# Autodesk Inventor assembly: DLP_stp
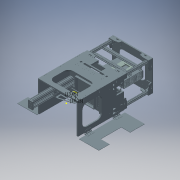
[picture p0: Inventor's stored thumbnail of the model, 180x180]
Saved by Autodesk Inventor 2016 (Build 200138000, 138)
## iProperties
Created: 2016-01
Part Number: DLP_stp
Document SubType Name: Assembly
Designer: John
Sending System: SIEMENS PLM Software NX 7.5
Preprocessor: ST-DEVELOPER v11
Title: DLP_stp.stp
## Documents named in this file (21)
- D:\3D Printer Designs\John Ledden Designs\DLP Printer\V2\DLP_stp.iam
- D:\3D Printer Designs\John Ledden Designs\DLP Printer\V2\VAT_ASSM.iam
- D:\3D Printer Designs\John Ledden Designs\DLP Printer\V2\91185A909_step.ipt
- D:\3D Printer Designs\John Ledden Designs\DLP Printer\V2\FRAME_ZMount.ipt
- D:\3D Printer Designs\John Ledden Designs\DLP Printer\V2\FRAME_SideWindow.ipt
- D:\3D Printer Designs\John Ledden Designs\DLP Printer\V2\VatHolder.ipt
- D:\3D Printer Designs\John Ledden Designs\DLP Printer\V2\FRAME_Rear.ipt
- D:\3D Printer Designs\John Ledden Designs\DLP Printer\V2\Frame_Mid.ipt
- D:\3D Printer Designs\John Ledden Designs\DLP Printer\V2\CornerBracket.ipt
- D:\3D Printer Designs\John Ledden Designs\DLP Printer\V2\CornerBracket_Projector.ipt
- D:\3D Printer Designs\John Ledden Designs\DLP Printer\V2\TSlot_300mm.ipt
- D:\3D Printer Designs\John Ledden Designs\DLP Printer\V2\FRAME_Base.ipt
- D:\3D Printer Designs\John Ledden Designs\DLP Printer\V2\projector_stp.ipt
- D:\3D Printer Designs\John Ledden Designs\DLP Printer\V2\TSlot_450mm.ipt
- D:\3D Printer Designs\John Ledden Designs\DLP Printer\V2\Projector_Plate.ipt
- D:\3D Printer Designs\John Ledden Designs\DLP Printer\V2\C-Beam Linear Actuator 500mm_step.iam
- D:\3D Printer Designs\John Ledden Designs\DLP Printer\V2\FrontBrace.ipt
- D:\3D Printer Designs\John Ledden Designs\DLP Printer\V2\Hinge_step.ipt
- D:\3D Printer Designs\John Ledden Designs\DLP Printer\V2\Door.ipt
- D:\3D Printer Designs\John Ledden Designs\DLP Printer\V2\FanVent_Projector.ipt
- D:\3D Printer Designs\John Ledden Designs\DLP Printer\V2\BED_ASSM.iam
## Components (37 placed, 37 different names)
1. VAT_ASSM_1070 [sub-assembly]
2. 91185A909_step_1071
3. 91185A909_step_1072
4. 91185A909_step_1073
5. 91185A909_step_1074
6. FRAME_ZMount_1075
7. FRAME_SideWindow_1076
8. VatHolder_1077
9. FRAME_Rear_1078
10. Frame_Mid_1079
11. CornerBracket_1080
12. CornerBracket_1081
13. CornerBracket_Projector_1082
14. CornerBracket_1083
15. TSlot_300mm_1084
16. TSlot_300mm_1085
17. TSlot_300mm_1086
18. TSlot_300mm_1087
19. CornerBracket_1088
20. CornerBracket_1089
21. CornerBracket_1090
22. CornerBracket_1091
23. FRAME_Base_1092
24. projector_stp_1093
25. TSlot_450mm_1094
26. TSlot_450mm_1095
27. Projector_Plate_1096
28. C-Beam Linear Actuator 500mm_step_1097 [sub-assembly]
29. FrontBrace_1098
30. Hinge_step_1099
31. Hinge_step_1100
32. Hinge_step_1101
33. Hinge_step_1102
34. Door_1103
35. Door_1104
36. FanVent_Projector_1105
37. BED_ASSM_1106 [sub-assembly]
